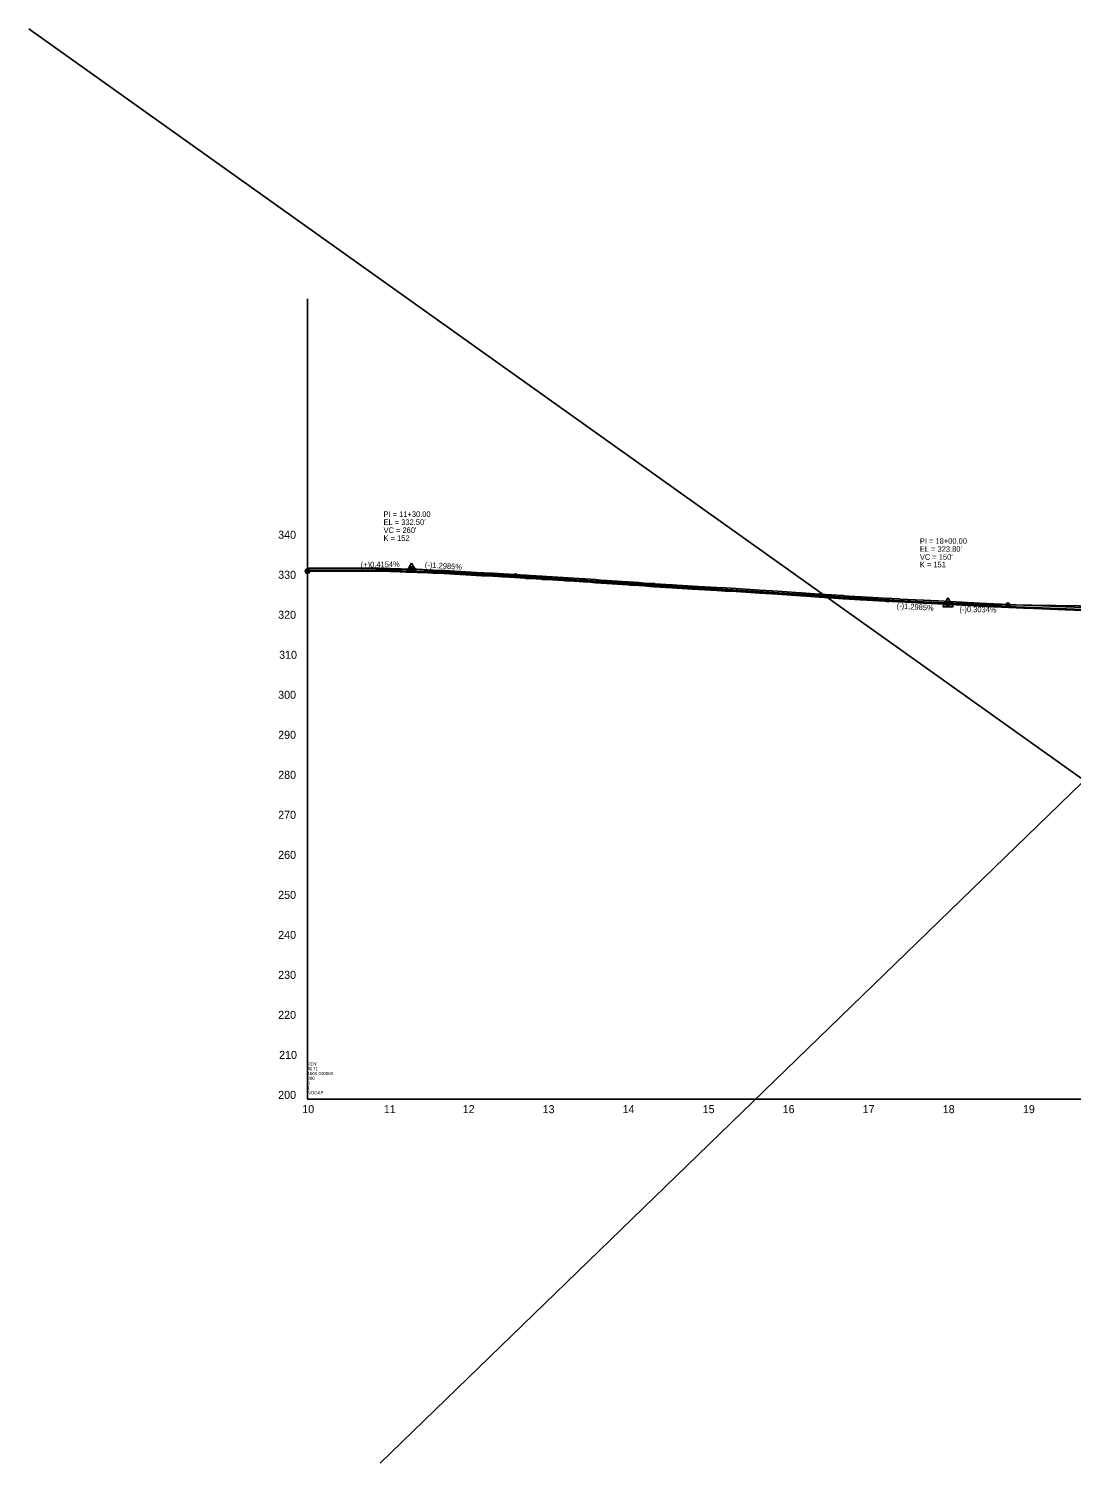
# Model space of a CAD drawing. Extents: x 2111382 to 2119088, y 667477 to 672158.
# Drawn here: x 2116484 to 2117786, y 670365 to 672158 of the extents above; entities that cross this region are included whole.
import ezdxf

# ---------------------------------------------------------------- set-up
doc = ezdxf.new("R2010")
doc.units = 0
for name, color, linetype in [('Exist Profile Cell', 7, 'Continuous'), ('Exist Vertical Profile Ground Line', 7, 'Continuous'), ('Exist Vertical Profile Horizontal Axis Label Major', 7, 'Continuous'), ('Exist Vertical Profile Vertical Axis Label', 7, 'Continuous'), ('Prop PFL VPI Symbol CELL', 7, 'Continuous'), ('Prop Vertical Profile Curve Label', 7, 'Continuous'), ('Prop Vertical Profile Grade', 7, 'Continuous'), ('Prop Vertical Profile Grade Label', 7, 'Continuous'), ('Prop VPI Label', 7, 'Continuous'), ('Scratch_Level_2', 7, 'Continuous'), ('Scratch_Level_3', 7, 'Continuous')]:
    doc.layers.add(name, color=color, linetype=linetype)

msp = doc.modelspace()

# ---------------------------------------------------------------- linework, layer by layer
at = {"layer": 'Exist Profile Cell'}
for q in [(2116831.9, 671820.2), (2119088.5, 670820.2), (2116831.9, 670820.2)]:
    msp.add_line((2116831.9, 670820.2), q, dxfattribs=at)
at = {"layer": 'Exist Vertical Profile Ground Line'}
for points in [[(2116831.9, 671480), (2116862, 671480.1), (2116867.4, 671480.1), (2116874.2, 671480.1), (2116880.9, 671480.1), (2116887.7, 671480.1), (2116891.5, 671480.1), (2116892, 671480.1), (2116894.4, 671480.1), (2116901.2, 671480.1), (2116907.9, 671480.1), (2116914.7, 671480.1), (2116918.3, 671480.1), (2116921.5, 671480), (2116928.2, 671479.8), (2116935, 671479.6), (2116941.7, 671479.4), (2116947.6, 671479.2), (2116948.5, 671479.1), (2116955.3, 671478.9), (2116962, 671478.7), (2116968.8, 671478.5), (2116973, 671478.4), (2116973.4, 671478.4), (2116973.9, 671478.3), (2116975.5, 671478.3), (2116982.3, 671477.9), (2116989.1, 671477.6), (2116995.8, 671477.3), (2117002.6, 671476.9), (2117003.4, 671476.9), (2117009.3, 671476.6), (2117016.1, 671476.3), (2117022.5, 671475.9), (2117022.9, 671475.9), (2117029.6, 671475.5), (2117036.4, 671475.1), (2117043.1, 671474.7), (2117049.9, 671474.3), (2117051.9, 671474.2), (2117052.6, 671474.2), (2117056.6, 671474), (2117063.4, 671473.6), (2117070.2, 671473.2), (2117075.3, 671472.9), (2117075.8, 671472.8), (2117076.9, 671472.8), (2117083.7, 671472.3), (2117090.4, 671471.9), (2117097.2, 671471.5), (2117104, 671471.1), (2117105, 671471), (2117105.8, 671471), (2117110.7, 671470.7), (2117117.5, 671470.3), (2117124.2, 671469.9), (2117124.6, 671469.8), (2117125, 671469.8), (2117131, 671469.4), (2117137.8, 671469), (2117144.5, 671468.6), (2117151.3, 671468.2), (2117154.3, 671468), (2117155, 671468), (2117155.4, 671468), (2117158, 671467.8), (2117164.8, 671467.4), (2117171.5, 671467), (2117176.1, 671466.7), (2117178.3, 671466.6), (2117185.1, 671466.1), (2117191.8, 671465.6), (2117198.6, 671465.2), (2117205.3, 671464.7), (2117206.1, 671464.7), (2117212.1, 671464.2), (2117218.9, 671463.8), (2117225.6, 671463.3), (2117232.4, 671462.8), (2117235.2, 671462.7), (2117235.7, 671462.6), (2117239.1, 671462.4), (2117245.9, 671461.9), (2117252.7, 671461.5), (2117259.4, 671461), (2117264.9, 671460.6), (2117265.7, 671460.6), (2117266.2, 671460.5), (2117272.9, 671460.1), (2117279.7, 671459.6), (2117286.5, 671459.2), (2117287.3, 671459.1), (2117287.8, 671459.1), (2117293.2, 671458.7), (2117300, 671458.3), (2117306.7, 671457.9), (2117312.5, 671457.6), (2117312.9, 671457.6), (2117313.6, 671457.5), (2117320.2, 671457.1), (2117343.1, 671455.9)], [(2117343.1, 671455.9), (2117354.1, 671455.2), (2117367.4, 671454.5), (2117397.1, 671452.7), (2117397.5, 671452.6), (2117419.1, 671451.3), (2117448.3, 671449.2), (2117449.1, 671449.1), (2117471.3, 671447.5), (2117471.9, 671447.4), (2117501.1, 671445.6), (2117501.9, 671445.6), (2117522.2, 671444.3), (2117522.7, 671444.3), (2117523.4, 671444.3), (2117552.7, 671442.6), (2117571.3, 671441.5), (2117571.9, 671441.5), (2117601.1, 671440.1), (2117601.9, 671440), (2117619.4, 671439.2), (2117619.8, 671439.2), (2117649.9, 671437.6), (2117656.3, 671437.3), (2117679.7, 671436), (2117680, 671436), (2117698.8, 671435), (2117726.5, 671433.9), (2117728.8, 671433.8), (2117749.5, 671432.8), (2117779, 671431.8), (2117779.5, 671431.7), (2117779.9, 671431.7), (2117800.2, 671431)]]:
    msp.add_lwpolyline(points, dxfattribs=at)
at = {"layer": 'Prop PFL VPI Symbol CELL'}
for p, q in [((2116961.9, 671490.2), (2116955.4, 671479)), ((2116961.9, 671490.2), (2116968.4, 671479)), ((2116955.4, 671479), (2116968.4, 671479)), ((2117631.9, 671446.7), (2117625.4, 671435.5)), ((2117625.4, 671435.5), (2117638.4, 671435.5)), ((2117631.9, 671446.7), (2117638.4, 671435.5))]:
    msp.add_line(p, q, dxfattribs=at)
for centre, radius in [((2116961.9, 671482.7), 1.75), ((2116961.9, 671482.7), 1.2), ((2117631.9, 671439.2), 1.75), ((2117631.9, 671439.2), 1.2)]:
    msp.add_circle(centre, radius, dxfattribs=at)
at = {"layer": 'Prop Vertical Profile Curve Label'}
for centre in [(2116831.9, 671480), (2117091.9, 671474.3), (2117556.9, 671444.1), (2117706.9, 671438.1)]:
    msp.add_circle(centre, 2.25, dxfattribs=at)
at = {"layer": 'Prop Vertical Profile Grade'}
for p, q in [((2117091.9, 671474.3), (2117556.9, 671444.1)), ((2117706.9, 671438.1), (2117976.9, 671434))]:
    msp.add_line(p, q, dxfattribs=at)
for points in [[(2116831.9, 671480), (2116837.1, 671480.1), (2116842.3, 671480.2), (2116847.5, 671480.3), (2116852.7, 671480.4), (2116857.9, 671480.5), (2116863.1, 671480.5), (2116868.3, 671480.6), (2116873.5, 671480.6), (2116878.7, 671480.6), (2116883.9, 671480.7), (2116889.1, 671480.7), (2116894.3, 671480.7), (2116899.5, 671480.7), (2116904.7, 671480.7), (2116909.9, 671480.7), (2116915.1, 671480.6), (2116920.3, 671480.6), (2116925.5, 671480.5), (2116930.7, 671480.5), (2116935.9, 671480.4), (2116941.1, 671480.3), (2116946.3, 671480.3), (2116951.5, 671480.2), (2116956.7, 671480.1), (2116961.9, 671479.9), (2116967.1, 671479.8), (2116972.3, 671479.7), (2116977.5, 671479.6), (2116982.7, 671479.4), (2116987.9, 671479.3), (2116993.1, 671479.1), (2116998.3, 671478.9), (2117003.5, 671478.7), (2117008.7, 671478.6), (2117013.9, 671478.4), (2117019.1, 671478.1), (2117024.3, 671477.9), (2117029.5, 671477.7), (2117034.7, 671477.5), (2117039.9, 671477.2), (2117045.1, 671477), (2117050.3, 671476.7), (2117055.5, 671476.4), (2117060.7, 671476.2), (2117065.9, 671475.9), (2117071.1, 671475.6), (2117076.3, 671475.3), (2117081.5, 671475), (2117086.7, 671474.6), (2117091.9, 671474.3)], [(2117556.9, 671444.1), (2117559.9, 671443.9), (2117562.9, 671443.7), (2117565.9, 671443.5), (2117568.9, 671443.3), (2117571.9, 671443.2), (2117574.9, 671443), (2117577.9, 671442.8), (2117580.9, 671442.6), (2117583.9, 671442.5), (2117586.9, 671442.3), (2117589.9, 671442.1), (2117592.9, 671442), (2117595.9, 671441.8), (2117598.9, 671441.7), (2117601.9, 671441.5), (2117604.9, 671441.4), (2117607.9, 671441.2), (2117610.9, 671441.1), (2117613.9, 671440.9), (2117616.9, 671440.8), (2117619.9, 671440.7), (2117622.9, 671440.5), (2117625.9, 671440.4), (2117628.9, 671440.3), (2117631.9, 671440.2), (2117634.9, 671440), (2117637.9, 671439.9), (2117640.9, 671439.8), (2117643.9, 671439.7), (2117646.9, 671439.6), (2117649.9, 671439.5), (2117652.9, 671439.4), (2117655.9, 671439.3), (2117658.9, 671439.2), (2117661.9, 671439.1), (2117664.9, 671439), (2117667.9, 671438.9), (2117670.9, 671438.9), (2117673.9, 671438.8), (2117676.9, 671438.7), (2117679.9, 671438.6), (2117682.9, 671438.6), (2117685.9, 671438.5), (2117688.9, 671438.4), (2117691.9, 671438.4), (2117694.9, 671438.3), (2117697.9, 671438.2), (2117700.9, 671438.2), (2117703.9, 671438.1), (2117706.9, 671438.1)]]:
    msp.add_spline(points, degree=3, dxfattribs=at)
at = {"layer": 'Prop VPI Label'}
for p, q in [((2116831.9, 671480), (2116959.1, 671482.7)), ((2117091.9, 671474.3), (2116964.6, 671482.6)), ((2117556.9, 671444.1), (2117629.1, 671439.4)), ((2117706.9, 671438.1), (2117634.6, 671439.2))]:
    msp.add_line(p, q, dxfattribs=at)
for centre in [(2116831.9, 671480), (2116961.9, 671482.7), (2117631.9, 671439.2)]:
    msp.add_circle(centre, 2.75, dxfattribs=at)
at = {"layer": 'Scratch_Level_2'}
for points in [[(2116831.9, 671481.3), (2116862, 671481.3), (2116867.4, 671481.3), (2116874.2, 671481.3), (2116880.9, 671481.3), (2116887.7, 671481.3), (2116891.5, 671481.3), (2116892, 671481.3), (2116894.4, 671481.3), (2116901.2, 671481.3), (2116907.9, 671481.3), (2116914.7, 671481.3), (2116918.3, 671481.3), (2116921.5, 671481.2), (2116928.2, 671481), (2116935, 671480.8), (2116941.7, 671480.6), (2116947.6, 671480.4), (2116948.5, 671480.4), (2116955.3, 671480.2), (2116962, 671480), (2116968.8, 671479.8), (2116973, 671479.6), (2116973.4, 671479.6), (2116973.9, 671479.6), (2116975.5, 671479.5), (2116982.3, 671479.2), (2116989.1, 671478.9), (2116995.8, 671478.5), (2117002.6, 671478.2), (2117003.4, 671478.1), (2117009.3, 671477.8), (2117016.1, 671477.5), (2117022.5, 671477.2), (2117022.9, 671477.2), (2117029.6, 671476.8), (2117036.4, 671476.4), (2117043.1, 671476), (2117049.9, 671475.6), (2117051.9, 671475.5), (2117052.6, 671475.4), (2117056.6, 671475.2), (2117063.4, 671474.8), (2117070.2, 671474.4), (2117075.3, 671474.1), (2117075.8, 671474.1), (2117076.9, 671474), (2117083.7, 671473.6), (2117090.4, 671473.2), (2117097.2, 671472.8), (2117104, 671472.4), (2117105, 671472.3), (2117105.8, 671472.2), (2117110.7, 671471.9), (2117117.5, 671471.5), (2117124.2, 671471.1), (2117124.6, 671471.1), (2117125, 671471.1), (2117131, 671470.7), (2117137.8, 671470.3), (2117144.5, 671469.9), (2117151.3, 671469.5), (2117154.3, 671469.3), (2117155, 671469.2), (2117155.4, 671469.2), (2117158, 671469.1), (2117164.8, 671468.6), (2117171.5, 671468.2), (2117176.1, 671468), (2117178.3, 671467.8), (2117185.1, 671467.4), (2117191.8, 671466.9), (2117198.6, 671466.4), (2117205.3, 671466), (2117206.1, 671465.9), (2117212.1, 671465.5), (2117218.9, 671465), (2117225.6, 671464.6), (2117232.4, 671464.1), (2117235.2, 671463.9), (2117235.7, 671463.9), (2117239.1, 671463.6), (2117245.9, 671463.2), (2117252.7, 671462.7), (2117259.4, 671462.3), (2117264.9, 671461.9), (2117265.7, 671461.8), (2117266.2, 671461.8), (2117272.9, 671461.3), (2117279.7, 671460.9), (2117286.5, 671460.4), (2117287.3, 671460.4), (2117287.8, 671460.3), (2117293.2, 671460), (2117300, 671459.6), (2117306.7, 671459.2), (2117312.5, 671458.8), (2117312.9, 671458.8), (2117313.6, 671458.8), (2117320.2, 671458.4), (2117343.1, 671457.1)], [(2117343.1, 671457.1), (2117354.1, 671456.5), (2117367.4, 671455.7), (2117397.1, 671453.9), (2117397.5, 671453.9), (2117419.1, 671452.6), (2117448.3, 671450.4), (2117449.1, 671450.4), (2117471.3, 671448.7), (2117471.9, 671448.7), (2117501.1, 671446.9), (2117501.9, 671446.8), (2117522.2, 671445.6), (2117522.7, 671445.5), (2117523.4, 671445.5), (2117552.7, 671443.8), (2117571.3, 671442.8), (2117571.9, 671442.7), (2117601.1, 671441.3), (2117601.9, 671441.3), (2117619.4, 671440.5), (2117619.8, 671440.4), (2117649.9, 671438.9), (2117656.3, 671438.5), (2117679.7, 671437.3), (2117680, 671437.3), (2117698.8, 671436.3), (2117726.5, 671435.1), (2117728.8, 671435), (2117749.5, 671434.1), (2117779, 671433), (2117779.5, 671433), (2117779.9, 671433), (2117800.2, 671432.2)]]:
    msp.add_lwpolyline(points, dxfattribs=at)
at = {"layer": 'Scratch_Level_3'}
for p, q in [((2116483.7, 672157.9), (2118975.5, 670382)), ((2116922.9, 670365.1), (2118570, 671963.4))]:
    msp.add_line(p, q, dxfattribs=at)
for points in [[(2116831.9, 671483.8), (2116862, 671483.8), (2116867.4, 671483.8), (2116874.2, 671483.8), (2116880.9, 671483.8), (2116887.7, 671483.8), (2116891.5, 671483.8), (2116892, 671483.8), (2116894.4, 671483.8), (2116901.2, 671483.8), (2116907.9, 671483.8), (2116914.7, 671483.8), (2116918.3, 671483.8), (2116921.5, 671483.7), (2116928.2, 671483.5), (2116935, 671483.3), (2116941.7, 671483.1), (2116947.6, 671482.9), (2116948.5, 671482.9), (2116955.3, 671482.7), (2116962, 671482.5), (2116968.8, 671482.3), (2116973, 671482.1), (2116973.4, 671482.1), (2116973.9, 671482.1), (2116975.5, 671482), (2116982.3, 671481.7), (2116989.1, 671481.4), (2116995.8, 671481), (2117002.6, 671480.7), (2117003.4, 671480.6), (2117009.3, 671480.3), (2117016.1, 671480), (2117022.5, 671479.7), (2117022.9, 671479.7), (2117029.6, 671479.3), (2117036.4, 671478.9), (2117043.1, 671478.5), (2117049.9, 671478.1), (2117051.9, 671478), (2117052.6, 671477.9), (2117056.6, 671477.7), (2117063.4, 671477.3), (2117070.2, 671476.9), (2117075.3, 671476.6), (2117075.8, 671476.6), (2117076.9, 671476.5), (2117083.7, 671476.1), (2117090.4, 671475.7), (2117097.2, 671475.3), (2117104, 671474.9), (2117105, 671474.8), (2117105.8, 671474.7), (2117110.7, 671474.4), (2117117.5, 671474), (2117124.2, 671473.6), (2117124.6, 671473.6), (2117125, 671473.6), (2117131, 671473.2), (2117137.8, 671472.8), (2117144.5, 671472.4), (2117151.3, 671472), (2117154.3, 671471.8), (2117155, 671471.7), (2117155.4, 671471.7), (2117158, 671471.6), (2117164.8, 671471.1), (2117171.5, 671470.7), (2117176.1, 671470.5), (2117178.3, 671470.3), (2117185.1, 671469.9), (2117191.8, 671469.4), (2117198.6, 671468.9), (2117205.3, 671468.5), (2117206.1, 671468.4), (2117212.1, 671468), (2117218.9, 671467.5), (2117225.6, 671467.1), (2117232.4, 671466.6), (2117235.2, 671466.4), (2117235.7, 671466.4), (2117239.1, 671466.1), (2117245.9, 671465.7), (2117252.7, 671465.2), (2117259.4, 671464.8), (2117264.9, 671464.4), (2117265.7, 671464.3), (2117266.2, 671464.3), (2117272.9, 671463.8), (2117279.7, 671463.4), (2117286.5, 671462.9), (2117287.3, 671462.9), (2117287.8, 671462.8), (2117293.2, 671462.5), (2117300, 671462.1), (2117306.7, 671461.7), (2117312.5, 671461.3), (2117312.9, 671461.3), (2117313.6, 671461.3), (2117320.2, 671460.9), (2117343.1, 671459.6)], [(2117343.1, 671459.6), (2117354.1, 671459), (2117367.4, 671458.2), (2117397.1, 671456.4), (2117397.5, 671456.4), (2117419.1, 671455.1), (2117448.3, 671452.9), (2117449.1, 671452.9), (2117471.3, 671451.2), (2117471.9, 671451.2), (2117501.1, 671449.4), (2117501.9, 671449.3), (2117522.2, 671448.1), (2117522.7, 671448), (2117523.4, 671448), (2117552.7, 671446.3), (2117571.3, 671445.3), (2117571.9, 671445.2), (2117601.1, 671443.8), (2117601.9, 671443.8), (2117619.4, 671443), (2117619.8, 671442.9), (2117649.9, 671441.4), (2117656.3, 671441), (2117679.7, 671439.8), (2117680, 671439.8), (2117698.8, 671438.8), (2117726.5, 671437.6), (2117728.8, 671437.5), (2117749.5, 671436.6), (2117779, 671435.5), (2117779.5, 671435.5), (2117779.9, 671435.5), (2117800.2, 671434.7)]]:
    msp.add_lwpolyline(points, dxfattribs=at)

# ---------------------------------------------------------------- texts
at = {"layer": 'Exist Profile Cell'}
for s, p in [('ALT1', (2116831.9, 670856.2)), ('RDY', (2116831.9, 670862.2)), ('200', (2116831.9, 670844.2)), ('5', (2116831.9, 670838.2)), ('1000.000000', (2116831.9, 670850.2)), ('1', (2116831.9, 670832.2)), ('NOGAP', (2116831.9, 670826.2))]:
    msp.add_text(s, height=4, dxfattribs=at).set_placement(p)
at = {"layer": 'Exist Vertical Profile Horizontal Axis Label Major'}
for s, p in [('10', (2116825.4, 670802.7)), ('11', (2116927.3, 670802.7)), ('12', (2117025.8, 670802.7)), ('13', (2117125.7, 670802.7)), ('14', (2117225.5, 670802.7)), ('15', (2117325.6, 670802.7)), ('16', (2117425.5, 670802.7)), ('17', (2117525.4, 670802.7)), ('18', (2117625.5, 670802.7)), ('19', (2117725.6, 670802.7))]:
    msp.add_text(s, height=10, dxfattribs=at).set_placement(p)
at = {"layer": 'Exist Vertical Profile Vertical Axis Label'}
for s, p in [('340', (2116795.3, 671520.5)), ('330', (2116795.3, 671470.5)), ('320', (2116795.3, 671420.5)), ('310', (2116796.5, 671370.5)), ('300', (2116795.3, 671320.5)), ('290', (2116795.3, 671270.5)), ('280', (2116795.3, 671220.5)), ('270', (2116795.3, 671170.5)), ('260', (2116795.3, 671120.5)), ('250', (2116795.3, 671070.5)), ('240', (2116795.3, 671020.5)), ('230', (2116795.3, 670970.5)), ('220', (2116795.3, 670920.5)), ('210', (2116796.5, 670870.5)), ('200', (2116795.3, 670820.5))]:
    msp.add_text(s, height=10, dxfattribs=at).set_placement(p)
at = {"layer": 'Prop Vertical Profile Curve Label'}
for s, p in [("VC = 260'", (2116926.9, 671527.7)), ('K = 152', (2116926.9, 671517.8)), ("VC = 150'", (2117596.9, 671494.2)), ('K = 151', (2117596.9, 671484.7))]:
    msp.add_text(s, height=7, dxfattribs=at).set_placement(p)
at = {"layer": 'Prop Vertical Profile Grade Label'}
for s, rotation, p in [('(+)0.4154%', 1.1898, (2116898.5, 671484.4)), ('(-)1.2985%', 356.2853, (2116978.4, 671484.7)), ('(-)1.2985%', 356.2853, (2117567.7, 671433.4)), ('(-)0.3034%', 359.1308, (2117646.3, 671429))]:
    msp.add_text(s, height=7, rotation=rotation, dxfattribs=at).set_placement(p)
at = {"layer": 'Prop VPI Label'}
for s, p in [('PI = 11+30.00', (2116926.9, 671547.7)), ("EL = 332.50'", (2116926.9, 671537.7)), ('PI = 18+00.00', (2117596.9, 671514.2)), ("EL = 323.80'", (2117596.9, 671504.2))]:
    msp.add_text(s, height=7, dxfattribs=at).set_placement(p)

doc.saveas('drawing.dxf')
